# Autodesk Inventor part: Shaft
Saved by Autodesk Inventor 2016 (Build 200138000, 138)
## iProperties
Created: 2015-03
Part Number: Shaft
Material: Steel
Document SubType Name: Modeling
Designer: Uglješa
Density: 7.85 g/cm^3
Appearance: Steel
Mass: 435.505 g
Surface Area: 107.308 cm^2
Volume: 55.4783 cm^3
CustomPartVersion: 1
Author: Uglješa
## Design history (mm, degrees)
sketch "Main Sketch"
  geometry: L1 (0, 0)-(132, 0) reference; L2 (0, 0)-(0, 12.5); L3 (0, 12.5)-(12, 12.5); L4 (12, 12.5)-(12, 15); L5 (37, 15)-(37, 12.5); L6 (12, 15)-(37, 15); L7 (52, 12.5)-(52, 10); L8 (37, 12.5)-(52, 12.5); L9 (132, 10)-(132, 0); L10 (52, 10)-(132, 10)
  constraints: 20 end point, 5 vertical, 2 horizontal
  dimensions: "d3" = 25 diameter of L3 L1 (derived); "d4" = 30 diameter of L6 L1 (derived); "d5" = 25 diameter of L8 L1 (derived); "d28" = 20 diameter of L10 L1 (derived)
revolve "Revolution1" sketch "Main Sketch" stored, may be unused: angle "d6" = 0 deg
chamfer "Chamfer19" distance "d67" = 1; stored, may be unused: second distance "d68" = 0.125, angle "d69" = 45 deg
chamfer "Chamfer16" distance "d58" = 1; stored, may be unused: second distance "d59" = 0.125, angle "d60" = 45 deg
fillet "Fillet5" dims "d54" = 1
chamfer "Chamfer7" distance "d29" = 1; stored, may be unused: second distance "d30" = 0.125, angle "d31" = 45 deg
node "Keyway2"
fillet "Fillet3" dims "d21" = 1
chamfer "Chamfer3" distance "d14" = 1; stored, may be unused: second distance "d15" = 0.125, angle "d16" = 45 deg
chamfer "Chamfer4" distance "d18" = 1; stored, may be unused: second distance "d19" = 0.125, angle "d20" = 45 deg
body "Solid1"
feature "iFeature3:2"
other parameters: "d0" = 0, "d1" = 0, "d2" = 0
